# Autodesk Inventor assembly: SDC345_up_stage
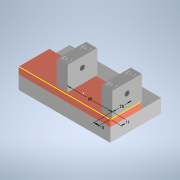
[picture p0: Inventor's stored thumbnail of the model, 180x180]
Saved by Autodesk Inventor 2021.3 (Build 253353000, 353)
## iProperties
Created: 2022-02
Part Number: SDC345_up_stage
Document SubType Name: Assembly
Designer: kengo
Author: kengo
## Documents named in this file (6)
- C:\Users\kengo\Documents\S2S_frame\SDC345\frame_misumi_ver12\upper-stage\SDC345_up_stage.iam
- C:\Users\kengo\Documents\S2S_frame\SDC345\frame_misumi_ver12\upper-stage\SDC_upper_stage_AlPlate.ipt
- C:\Users\kengo\Documents\S2S_frame\SDC345\frame_misumi_ver12\upper-stage\SDC_upper_stage_CFPlate.ipt
- C:\Users\kengo\Documents\S2S_frame\SDC345\frame_misumi_ver12\upper-stage\CBM12-25.ipt
- C:\Users\kengo\Documents\S2S_frame\SDC345\frame_misumi_ver12\upper-stage\AJSN8-20.ipt
- C:\Users\kengo\Documents\S2S_frame\SDC345\frame_misumi_ver12\upper-stage\SCB6-55.ipt
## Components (10 placed, 5 different names)
1. SDC_upper_stage_AlPlate:1 — 回転:1, 回転:2, メイト:1, フラッシュ:1, フラッシュ:2
2. SDC_upper_stage_CFPlate:1 — メイト:1, フラッシュ:1, フラッシュ:2, 挿入:1, 挿入:2, 挿入:3, 挿入:4
3. CBM12-25:1 — 回転:1
4. CBM12-25:2 — 回転:2
5. AJSN8-20:1 — 挿入:1, 挿入:4, 回転:3, 回転:4
6. AJSN8-20:2 — 挿入:2, 挿入:3, 回転:5, 回転:6
7. SCB6-55:1 — 回転:3
8. SCB6-55:2 — 回転:4
9. SCB6-55:3 — 回転:5
10. SCB6-55:4 — 回転:6
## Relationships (13: RevoluteJoint 6, Insert 4, Flush 2, Mate 1)
- 回転:1 [RevoluteJoint]: SDC_upper_stage_AlPlate:1 ↔ CBM12-25:1
- 回転:2 [RevoluteJoint]: SDC_upper_stage_AlPlate:1 ↔ CBM12-25:2
- メイト:1 [Mate]: SDC_upper_stage_AlPlate:1 ↔ SDC_upper_stage_CFPlate:1
- フラッシュ:1 [Flush]: SDC_upper_stage_AlPlate:1 ↔ SDC_upper_stage_CFPlate:1
- フラッシュ:2 [Flush]: SDC_upper_stage_AlPlate:1 ↔ SDC_upper_stage_CFPlate:1
- 挿入:1 [Insert]: SDC_upper_stage_CFPlate:1 ↔ AJSN8-20:1
- 挿入:2 [Insert]: SDC_upper_stage_CFPlate:1 ↔ AJSN8-20:2
- 挿入:3 [Insert]: SDC_upper_stage_CFPlate:1 ↔ AJSN8-20:2
- 挿入:4 [Insert]: SDC_upper_stage_CFPlate:1 ↔ AJSN8-20:1
- 回転:3 [RevoluteJoint]: AJSN8-20:1 ↔ SCB6-55:1
- 回転:4 [RevoluteJoint]: AJSN8-20:1 ↔ SCB6-55:2
- 回転:5 [RevoluteJoint]: AJSN8-20:2 ↔ SCB6-55:3
- 回転:6 [RevoluteJoint]: AJSN8-20:2 ↔ SCB6-55:4
